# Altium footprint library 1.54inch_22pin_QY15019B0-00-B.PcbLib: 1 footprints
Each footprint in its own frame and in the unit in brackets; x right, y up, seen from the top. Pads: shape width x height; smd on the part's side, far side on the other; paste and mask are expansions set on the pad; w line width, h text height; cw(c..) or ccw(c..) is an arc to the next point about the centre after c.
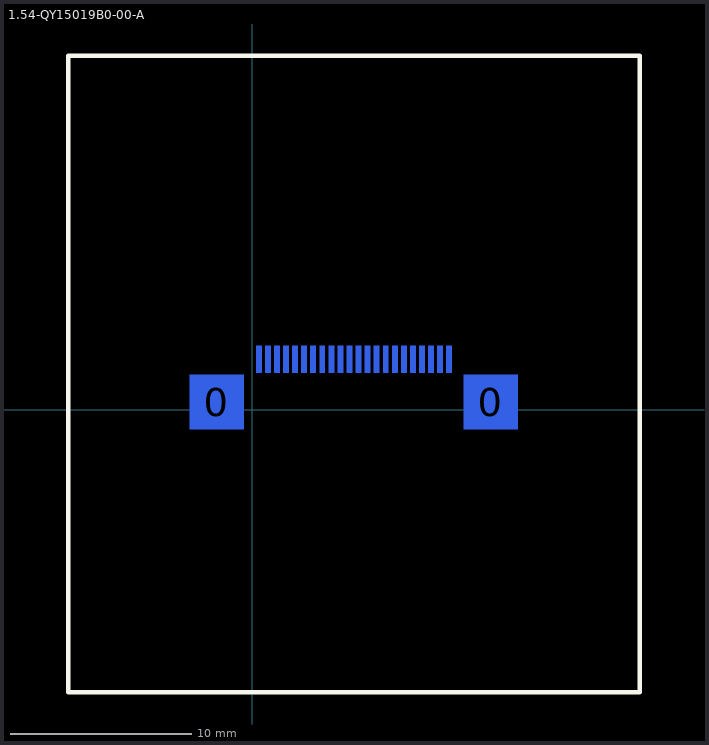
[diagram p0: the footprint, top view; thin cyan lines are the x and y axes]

## 1.54-QY15019B0-00-A [mm] "1.54 TFT IPS"
pads (24):
  rect 3x3 smd far side: 0(-1.967,0.42) 0(13.149,0.42)
  rect 0.3x1.5 smd far side: 1(0.355,2.79) 2(0.855,2.79) 3(1.355,2.79) 4(1.855,2.79) 5(2.355,2.79) 6(2.855,2.79) 7(3.355,2.79) 8(3.855,2.79) 9(4.355,2.79) 10(4.855,2.79) 11(5.355,2.79) 12(5.855,2.79) 13(6.355,2.79) 14(6.855,2.79) 15(7.355,2.79) 16(7.855,2.79) 17(8.355,2.79) 18(8.855,2.79) 19(9.355,2.79) 20(9.855,2.79) 21(10.355,2.79) 22(10.855,2.79)
Top Overlay:
  lines w0.254: -10.155,-15.58 21.365,-15.58 21.365,19.52 -10.155,19.52 -10.155,-15.58
Bottom Overlay:
  lines w0.2: -3.77,-1.712 -3.77,1.641 ; -3.77,-1.178 -3.77,-3.007 14.978,-3.007 14.978,-1.305 ; -3.77,1.286 -3.77,2.632 -0.392,2.632 -0.392,4.207 11.599,4.207 11.599,2.536 12.021,2.536 14.978,2.536 14.978,2.121 14.978,1.159 ; 14.978,-1.839 14.978,1.514
  text "1" at -1.14,2.875 h1.02
  text "22" at 13.911,2.835 h1.02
